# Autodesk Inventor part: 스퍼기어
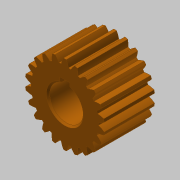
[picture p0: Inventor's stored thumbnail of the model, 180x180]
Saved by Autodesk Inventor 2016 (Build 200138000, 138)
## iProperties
Created: 2019-03
Part Number: 스퍼기어
Material: 강철
Document SubType Name: Modeling
Designer: mduedu
Categories: <?xml version="1.0" encoding="UTF-16"?> <MemberInstance><Categories><FamilyTemplate><FamilyTemplateParameter ValueType="xs:double" Id="1" ObjectReferenceKey="da
Density: 1 g/cm^3
Appearance: 주황색
CustomPartVersion: 1
Author: mduedu
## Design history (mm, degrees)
sketch "Sketch1"
  geometry: C1 r 23.6 at (0, 0)
  constraints: 1 centre point
  dimensions: "d0" = 47.2 diameter of C1 (= da_da)
extrude "Extrusion1" new body sketch "Sketch1" distance "d1" = 30 (= da_b); taper "d2" = 0 deg
workplane "Work Plane2"
sketch "Sketch2"
  geometry: C1 r 23.6 at (0, 0) reference; C2 r 22 at (0, 0)
  constraints: 1 centre point, 1 coincident
  dimensions: "d3" = 44 diameter of C2 (= da_dw)
feature "피치 지름" sketch "Sketch2" dims "d4" = 10, "d5" = 0
workplane "Work Plane8"
workplane "Work Plane9"
feature "스퍼 기어" dims "d0" = 47.2 (= da_da), "da_b" = 30, "da_d" = 44, "da_aw" = 44, "da_da" = 47.2, "da_df" = 40.172, "da_dw" = 44, angle "da_beta" = 0 deg, "da_lefttooth" = 0, "da_righttooth" = 0
sketch "스케치3"
  geometry: L1 (-3, 9.539)-(3, 9.539); L2 (3, 9.539)-(3, 12.8); L3 (3, 12.8)-(-3, 12.8); L4 (-3, 12.8)-(-3, 9.539); A1 r 10 centre (0, 0) between (-3, 9.539) and (3, 9.539); 1 further point
  constraints: 8 end point, 2 parallel, 2 point on circle, 1 centre point, 1 coincident, 1 horizontal, 1 perpendicular
  dimensions: "d49" = 20 diameter of A1; "d50" = 6 distance of L2.end L3.end; "d51" = 22.8 dimension on A1 L3
extrude "돌출2" cut sketch "스케치3" stored distance "d52" = 10; taper "d53" = 0 deg
chamfer "모따기1" distance "d54" = 1; stored, may be unused: second distance "d55" = 2, angle "d56" = 45 deg
body "Solid1"
body "Srf1"
other parameters: "d16" = 44 (= da_aw), "d17" = 0, "d34" = 1.428 (computed from da_z), "d39" = 0, "d41" = 0, "d43" = 44 (= da_aw), "d46" = 44 (= da_aw), "d47" = 0, "d48" = 0
